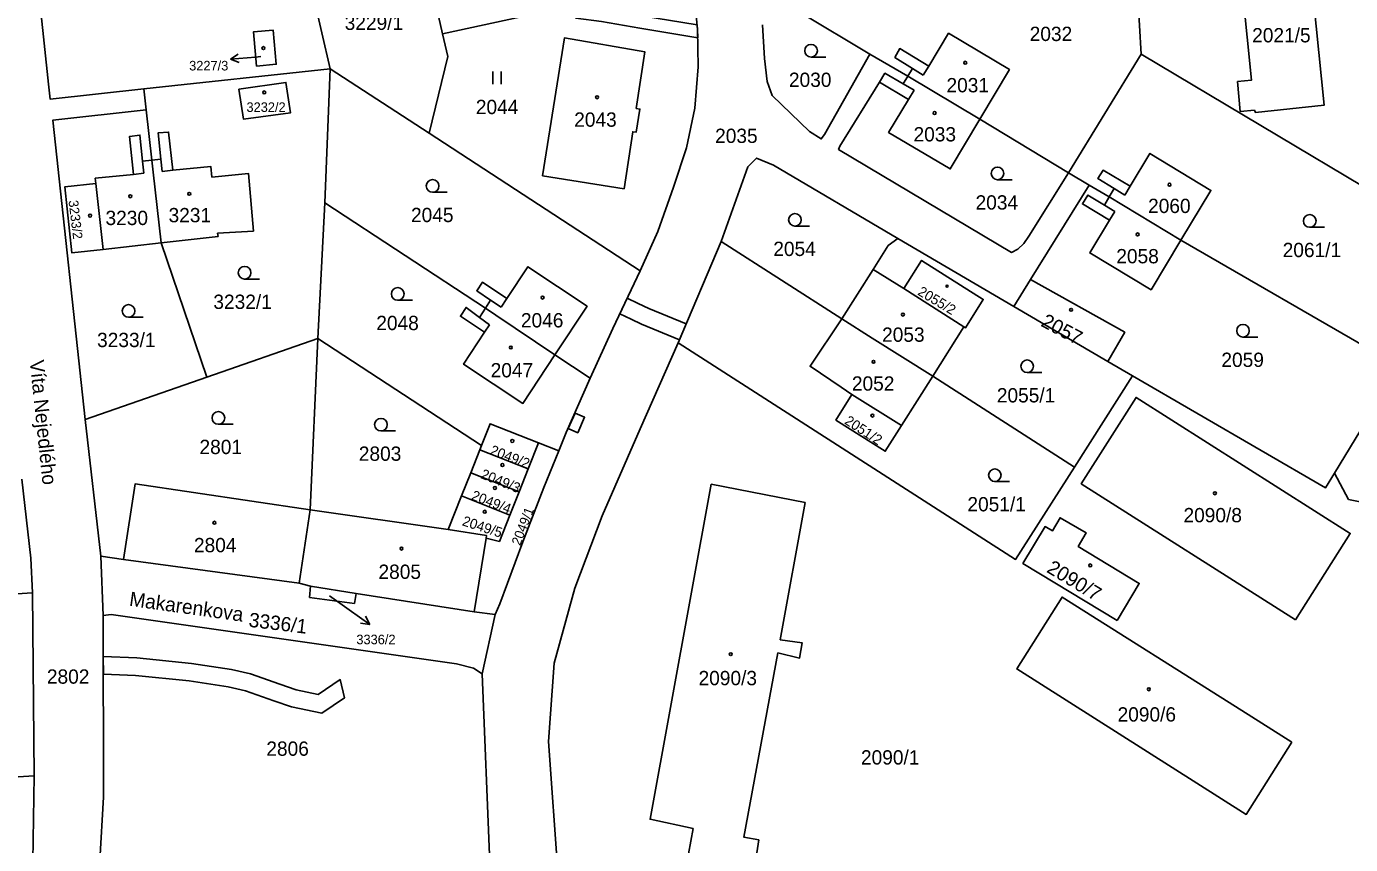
# Model space of a CAD drawing. Extents: x -869103 to -863415, y -1015889 to -1012477.
# Drawn here: x -866307 to -866149.5, y -1014543.4 to -1014446.1 of the extents above; entities that cross this region are included whole.
import ezdxf

# ---------------------------------------------------------------- set-up
doc = ezdxf.new("R2010")
doc.units = 0
for name, color, linetype in [('Hranice parcel', 7, 'Continuous'), ('Parcelní čísla', 7, 'Continuous'), ('Pop  PČ popisy', 7, 'Continuous'), ('Vnitřní kresba', 7, 'Continuous'), ('Věcná břemena k části', 7, 'Continuous'), ('Značky budov', 7, 'Continuous'), ('Značky kultur', 7, 'Continuous')]:
    doc.layers.add(name, color=color, linetype=linetype)

msp = doc.modelspace()

# ---------------------------------------------------------------- linework, layer by layer
at = {"layer": 'Hranice parcel'}
for p, q in [((-866175.13, -1014436.7), (-866174.38, -1014449.43)), ((-866273.58, -1014439.3), (-866270.86, -1014451.16)), ((-866257.47, -1014447.01), (-866246.67, -1014444.68)), ((-866206.66, -1014449.41), (-866214.86, -1014444.49)), ((-866206.66, -1014449.41), (-866202.12, -1014452.04)), ((-866183.01, -1014463.54), (-866174.38, -1014449.43)), ((-866135.49, -1014472.62), (-866174.38, -1014449.43)), ((-866293.01, -1014453.56), (-866270.86, -1014451.16)), ((-866270.86, -1014451.16), (-866271.49, -1014467.09)), ((-866259.09, -1014458.82), (-866270.86, -1014451.16)), ((-866202.12, -1014452.04), (-866193.57, -1014457.16)), ((-866292.73, -1014456.06), (-866293.01, -1014453.56)), ((-866292.06, -1014462.04), (-866292.73, -1014456.06)), ((-866193.57, -1014457.16), (-866183.01, -1014463.54)), ((-866259.09, -1014458.82), (-866233.96, -1014475.17)), ((-866180.58, -1014464.98), (-866183.01, -1014463.54)), ((-866298.71, -1014464.78), (-866297.83, -1014472.64)), ((-866187.53, -1014476.22), (-866180.58, -1014464.98)), ((-866178.18, -1014466.39), (-866180.58, -1014464.98)), ((-866169.65, -1014471.53), (-866178.18, -1014466.39)), ((-866271.49, -1014467.09), (-866272.32, -1014483.22)), ((-866271.49, -1014467.09), (-866252.39, -1014479.64)), ((-866290.94, -1014471.86), (-866284.16, -1014471.12)), ((-866229.45, -1014483.76), (-866224.33, -1014471.68)), ((-866209.97, -1014480.9), (-866224.33, -1014471.68)), ((-866203.34, -1014471.34), (-866189.52, -1014479.44)), ((-866143.69, -1014486.53), (-866169.65, -1014471.53)), ((-866297.83, -1014472.64), (-866290.94, -1014471.86)), ((-866285.53, -1014487.82), (-866290.94, -1014471.86)), ((-866206.25, -1014475.01), (-866209.97, -1014480.9)), ((-866202.63, -1014477.3), (-866206.25, -1014475.01)), ((-866189.52, -1014479.44), (-866187.53, -1014476.22)), ((-866195.46, -1014481.85), (-866202.63, -1014477.3)), ((-866178.34, -1014485.95), (-866189.52, -1014479.44)), ((-866199.18, -1014487.72), (-866195.46, -1014481.85)), ((-866272.32, -1014483.22), (-866285.53, -1014487.82)), ((-866273.23, -1014503.59), (-866272.32, -1014483.22)), ((-866272.32, -1014483.22), (-866252.84, -1014495.95)), ((-866244.11, -1014485.17), (-866239.92, -1014487.93)), ((-866175.4, -1014487.66), (-866178.34, -1014485.95)), ((-866151.4, -1014499.23), (-866143.69, -1014486.53)), ((-866285.53, -1014487.82), (-866299.97, -1014492.85)), ((-866199.18, -1014487.72), (-866202.89, -1014493.59)), ((-866182.31, -1014498.51), (-866199.18, -1014487.72)), ((-866182.31, -1014498.51), (-866175.4, -1014487.66)), ((-866202.89, -1014493.59), (-866208.78, -1014489.87)), ((-866299.97, -1014492.85), (-866298.12, -1014509.12)), ((-866253.04, -1014496.45), (-866254.13, -1014499.18)), ((-866252.84, -1014495.95), (-866253.04, -1014496.45)), ((-866253.04, -1014496.45), (-866247.28, -1014498.74)), ((-866246.05, -1014495.65), (-866247.28, -1014498.74)), ((-866243.65, -1014496.6), (-866246.05, -1014495.65)), ((-866254.13, -1014499.18), (-866255.22, -1014501.93)), ((-866254.13, -1014499.18), (-866248.37, -1014501.47)), ((-866247.28, -1014498.74), (-866248.37, -1014501.47)), ((-866248.37, -1014501.47), (-866249.46, -1014504.22)), ((-866255.22, -1014501.93), (-866256.82, -1014505.95)), ((-866255.22, -1014501.93), (-866249.46, -1014504.22)), ((-866274.52, -1014512.32), (-866273.23, -1014503.59)), ((-866256.82, -1014505.95), (-866273.23, -1014503.59)), ((-866252.29, -1014506.96), (-866253.73, -1014515.71)), ((-866298.12, -1014509.12), (-866295.41, -1014509.5)), ((-866297.84, -1014516.17), (-866298.12, -1014509.12)), ((-866295.41, -1014509.5), (-866274.52, -1014512.32)), ((-866274.52, -1014512.32), (-866273.18, -1014512.66)), ((-866306.07, -1014535.23), (-866306.24, -1014513.48)), ((-866273.18, -1014512.66), (-866267.76, -1014513.55)), ((-866267.76, -1014513.55), (-866253.73, -1014515.71)), ((-866253.73, -1014515.71), (-866251.23, -1014516.05)), ((-866251.23, -1014516.05), (-866252.75, -1014523.11)), ((-866306.07, -1014535.23), (-866310.81, -1014535.52))]:
    msp.add_line(p, q, dxfattribs=at)
for points in [[(-866262.06, -1014426.88), (-866259.63, -1014437.54), (-866257.47, -1014447.01)], [(-866293.01, -1014453.56), (-866304.17, -1014454.77), (-866304.36, -1014453), (-866306.78, -1014430.1), (-866304.7, -1014428.53)], [(-866160.89, -1014456.08), (-866160.79, -1014456.34), (-866152.63, -1014455.5), (-866154.51, -1014436.67), (-866162.78, -1014437.55), (-866161.26, -1014452.53), (-866162.92, -1014452.68), (-866162.6, -1014456.23), (-866160.89, -1014456.08)], [(-866227.71, -1014440.6), (-866227.14, -1014446.48), (-866227.07, -1014450.92), (-866227.49, -1014455.83), (-866228.45, -1014460.55), (-866229.99, -1014465.24), (-866231.89, -1014470.52), (-866233.96, -1014475.17)], [(-866219.44, -1014445.94), (-866219.2, -1014449.92), (-866218.86, -1014452.67), (-866218.26, -1014454.34), (-866213.82, -1014458.63), (-866212.44, -1014459.5), (-866212.04, -1014458.99), (-866206.66, -1014449.41)], [(-866279.6, -1014450.83), (-866279.97, -1014446.77), (-866277.63, -1014446.56), (-866277.26, -1014450.62), (-866279.6, -1014450.83)], [(-866257.47, -1014447.01), (-866256.86, -1014449.69), (-866259.09, -1014458.82)], [(-866234.44, -1014455.89), (-866233.42, -1014449.13), (-866242.98, -1014447.5), (-866245.59, -1014463.88), (-866235.88, -1014465.42), (-866234.86, -1014458.64), (-866234.46, -1014458.7), (-866234.01, -1014455.96), (-866234.44, -1014455.89)], [(-866193.57, -1014457.16), (-866190.05, -1014451.25), (-866197.29, -1014446.93), (-866199.65, -1014450.83), (-866203.1, -1014448.75), (-866203.68, -1014449.81), (-866201.57, -1014451.12), (-866202.12, -1014452.04)], [(-866281.72, -1014453.59), (-866281.15, -1014457.16), (-866275.58, -1014456.41), (-866276.1, -1014452.78), (-866281.72, -1014453.59)], [(-866205.5, -1014452.74), (-866210.24, -1014460.35), (-866210.38, -1014460.75), (-866189.82, -1014472.99), (-866189.04, -1014472.6), (-866188.32, -1014471.93), (-866187.74, -1014471.06), (-866183.01, -1014463.54)], [(-866202.12, -1014452.04), (-866202.68, -1014452.96), (-866204.87, -1014451.69), (-866205.5, -1014452.74)], [(-866205.5, -1014452.74), (-866202.05, -1014454.81), (-866204.42, -1014458.72), (-866197.09, -1014463.07), (-866193.57, -1014457.16)], [(-866299.97, -1014492.85), (-866303.84, -1014457.28), (-866292.73, -1014456.06)], [(-866292.06, -1014462.04), (-866293.15, -1014462.15), (-866293.47, -1014459.05), (-866294.73, -1014459.22), (-866294.25, -1014463.71), (-866298.78, -1014464.17), (-866298.71, -1014464.78)], [(-866279.98, -1014470.45), (-866280.56, -1014463.63), (-866284.91, -1014464.04), (-866285.05, -1014462.76), (-866289.58, -1014463.23), (-866290.06, -1014458.69), (-866291.3, -1014458.77), (-866290.97, -1014461.92), (-866292.06, -1014462.04)], [(-866105.99, -1014458.82), (-866117.63, -1014476.02), (-866116.92, -1014476.56), (-866133.47, -1014498.56), (-866138.91, -1014504.56), (-866149.72, -1014502.36), (-866151.4, -1014499.23)], [(-866290.94, -1014471.86), (-866291.9, -1014463.46), (-866292.06, -1014462.04)], [(-866224.33, -1014471.68), (-866221.17, -1014462.82), (-866220.14, -1014461.77), (-866218.1, -1014462.6), (-866203.34, -1014471.34)], [(-866169.65, -1014471.53), (-866166.09, -1014465.62), (-866173.34, -1014461.22), (-866175.69, -1014465.11), (-866178.91, -1014463.22), (-866179.52, -1014464.21), (-866177.58, -1014465.4), (-866178.18, -1014466.39)], [(-866297.83, -1014472.64), (-866301.56, -1014473.06), (-866302.39, -1014465.19), (-866298.71, -1014464.78)], [(-866178.18, -1014466.39), (-866178.76, -1014467.36), (-866180.71, -1014466.18), (-866181.38, -1014467.22), (-866178.15, -1014469.17), (-866180.5, -1014473.06), (-866173.2, -1014477.44), (-866169.65, -1014471.53)], [(-866284.16, -1014471.12), (-866284.23, -1014470.71), (-866279.98, -1014470.45)], [(-866206.25, -1014475.01), (-866204.46, -1014472.18), (-866203.34, -1014471.34)], [(-866252.39, -1014479.64), (-866251.76, -1014478.67), (-866253.41, -1014477.55), (-866252.74, -1014476.54), (-866249.82, -1014478.47), (-866247.33, -1014474.7), (-866240.29, -1014479.4), (-866244.11, -1014485.17)], [(-866202.63, -1014477.3), (-866200.5, -1014473.94), (-866193.16, -1014478.59), (-866195.29, -1014481.96), (-866195.46, -1014481.85)], [(-866233.96, -1014475.17), (-866237.21, -1014482.04), (-866239.92, -1014487.93)], [(-866178.34, -1014485.95), (-866176.33, -1014482.49), (-866187.53, -1014476.22)], [(-866252.39, -1014479.64), (-866253.1, -1014480.72), (-866254.67, -1014479.54), (-866255.36, -1014480.59), (-866252.47, -1014482.49), (-866254.98, -1014486.29), (-866247.92, -1014490.94), (-866244.11, -1014485.17)], [(-866252.39, -1014479.64), (-866251.14, -1014480.47), (-866244.11, -1014485.17)], [(-866208.78, -1014489.87), (-866210.06, -1014489.01), (-866213.77, -1014486.52), (-866209.97, -1014480.9)], [(-866199.18, -1014487.72), (-866206.36, -1014483.18), (-866209.97, -1014480.9)], [(-866244.89, -1014531.13), (-866244.21, -1014521.83), (-866241.75, -1014512.93), (-866238.49, -1014504.31), (-866233.99, -1014493.98), (-866229.45, -1014483.76)], [(-866229.45, -1014483.76), (-866189.32, -1014509.5), (-866182.31, -1014498.51)], [(-866239.92, -1014487.93), (-866242.76, -1014494.42), (-866243.65, -1014496.6)], [(-866175.4, -1014487.66), (-866152.47, -1014500.99), (-866151.4, -1014499.23)], [(-866202.89, -1014493.59), (-866204.82, -1014496.64), (-866210.7, -1014492.92), (-866208.78, -1014489.87)], [(-866156.04, -1014516.66), (-866149.51, -1014506.4), (-866174.98, -1014490.24), (-866181.51, -1014500.5), (-866156.04, -1014516.66)], [(-866246.05, -1014495.65), (-866251.82, -1014493.36), (-866252.84, -1014495.95)], [(-866243.65, -1014496.6), (-866245.44, -1014500.95), (-866247.91, -1014507.39), (-866250.68, -1014514.78), (-866251.23, -1014516.05)], [(-866306.24, -1014513.48), (-866306.47, -1014509.33), (-866307.52, -1014499.97)], [(-866295.41, -1014509.5), (-866294.03, -1014500.49), (-866273.23, -1014503.59)], [(-866225.51, -1014500.55), (-866232.8, -1014540.38), (-866227.65, -1014541.5)], [(-866217.61, -1014520.61), (-866215.02, -1014521.23), (-866214.71, -1014519.41), (-866217.32, -1014519.04), (-866214.36, -1014502.74), (-866225.51, -1014500.55)], [(-866249.46, -1014504.22), (-866250.71, -1014507.36), (-866252.29, -1014506.96)], [(-866177.23, -1014516.77), (-866174.62, -1014512.35), (-866181.87, -1014507.95), (-866180.94, -1014506.32), (-866184.03, -1014504.54), (-866184.92, -1014506.09), (-866185.82, -1014505.58), (-866188.44, -1014509.97), (-866177.23, -1014516.77)], [(-866256.82, -1014505.95), (-866252.24, -1014506.66), (-866252.29, -1014506.96)], [(-866306.24, -1014513.48), (-866313.12, -1014513.9), (-866314.13, -1014513.97), (-866322.69, -1014514.6)], [(-866267.76, -1014513.55), (-866267.96, -1014514.72), (-866273.3, -1014514.01), (-866273.18, -1014512.66)], [(-866156.45, -1014531.23), (-866162.39, -1014527.47), (-866183.78, -1014513.98), (-866189.19, -1014522.52), (-866167.76, -1014536.09), (-866161.88, -1014539.81), (-866156.45, -1014531.23)], [(-866298.23, -1014545.3), (-866297.79, -1014537.75), (-866297.84, -1014516.17)], [(-866297.84, -1014516.17), (-866296.9, -1014516.03), (-866255.83, -1014521.91), (-866253.79, -1014522.42), (-866252.75, -1014523.11)], [(-866219.84, -1014542.82), (-866221.64, -1014542.52), (-866217.61, -1014520.61)], [(-866252.75, -1014523.11), (-866251.85, -1014545.62), (-866251.59, -1014552.32)], [(-866239.33, -1014563.34), (-866241.17, -1014558), (-866243.17, -1014550.45), (-866243.74, -1014547.16), (-866244.89, -1014531.13)], [(-866310.49, -1014570.24), (-866307.92, -1014562.25), (-866306.24, -1014547.91), (-866306.07, -1014535.23)], [(-866227.65, -1014541.5), (-866228.21, -1014544.51), (-866220.34, -1014545.93), (-866219.84, -1014542.82)]]:
    msp.add_lwpolyline(points, dxfattribs=at)
at = {"layer": 'Pop  PČ popisy'}
for p, q in [((-866282.72, -1014450.02), (-866281.77, -1014449.44)), ((-866279.73, -1014449.76), (-866282.72, -1014450.02)), ((-866282.72, -1014450.02), (-866281.68, -1014450.43)), ((-866279.09, -1014449.7), (-866279.73, -1014449.76)), ((-866270.91, -1014513.81), (-866268.57, -1014515.49)), ((-866268.57, -1014515.49), (-866266.14, -1014517.25)), ((-866266.14, -1014517.25), (-866267.25, -1014517.07)), ((-866266.14, -1014517.25), (-866266.66, -1014516.26))]:
    msp.add_line(p, q, dxfattribs=at)
at = {"layer": 'Vnitřní kresba'}
for p, q in [((-866201.57, -1014451.12), (-866200.31, -1014451.93)), ((-866200.31, -1014451.93), (-866199.65, -1014450.83)), ((-866202.68, -1014452.96), (-866201.39, -1014453.71)), ((-866201.39, -1014453.71), (-866202.05, -1014454.81)), ((-866293.15, -1014462.15), (-866293, -1014463.57)), ((-866290.97, -1014461.92), (-866290.82, -1014463.36)), ((-866293, -1014463.57), (-866294.25, -1014463.71)), ((-866290.82, -1014463.36), (-866289.58, -1014463.23)), ((-866177.58, -1014465.4), (-866176.33, -1014466.17)), ((-866176.33, -1014466.17), (-866175.69, -1014465.11)), ((-866178.76, -1014467.36), (-866177.51, -1014468.12)), ((-866177.51, -1014468.12), (-866178.15, -1014469.17)), ((-866250.51, -1014479.52), (-866251.76, -1014478.67)), ((-866250.51, -1014479.52), (-866249.82, -1014478.47)), ((-866251.9, -1014481.62), (-866253.1, -1014480.72)), ((-866252.47, -1014482.49), (-866251.9, -1014481.62))]:
    msp.add_line(p, q, dxfattribs=at)
at = {"layer": 'Věcná břemena k části'}
for points in [[(-866241.97, -1014443.67), (-866241.64, -1014445.13), (-866238.58, -1014445.54), (-866234.02, -1014446.33), (-866227.12, -1014447.48), (-866227.14, -1014446.48), (-866227.19, -1014445.94), (-866233.77, -1014444.85), (-866238.35, -1014444.06), (-866240.41, -1014443.78), (-866240.51, -1014443.36)], [(-866236.38, -1014480.29), (-866235.06, -1014480.92), (-866233.8, -1014481.53), (-866229.29, -1014483.38), (-866228.49, -1014481.5), (-866232.96, -1014479.67), (-866234.22, -1014479.06), (-866235.51, -1014478.45)], [(-866236.38, -1014480.29), (-866235.06, -1014480.92), (-866233.8, -1014481.53), (-866229.29, -1014483.38), (-866228.49, -1014481.5), (-866232.96, -1014479.67), (-866234.22, -1014479.06), (-866235.51, -1014478.45)], [(-866242.54, -1014493.92), (-866241.39, -1014494.43), (-866240.58, -1014492.59), (-866241.72, -1014492.09)], [(-866297.83, -1014521.03), (-866297.82, -1014523.12), (-866293.99, -1014523.29), (-866287.61, -1014523.94), (-866282.98, -1014524.64), (-866280.9, -1014525.1), (-866277.55, -1014526.32), (-866275.45, -1014527.02), (-866271.83, -1014527.77), (-866269.15, -1014525.97), (-866269.65, -1014523.79), (-866272.27, -1014525.55), (-866274.91, -1014525), (-866276.85, -1014524.34), (-866280.32, -1014523.08), (-866282.6, -1014522.58), (-866287.35, -1014521.86), (-866293.83, -1014521.21)]]:
    msp.add_lwpolyline(points, close=True, dxfattribs=at)
at = {"layer": 'Značky budov'}
for centre, radius in [((-866278.79, -1014448.7), 0.175), ((-866195.31, -1014450.44), 0.175), ((-866278.69, -1014453.97), 0.175), ((-866239.1, -1014454.54), 0.175), ((-866198.95, -1014456.42), 0.175), ((-866171.01, -1014464.94), 0.175), ((-866294.62, -1014466.32), 0.175), ((-866287.6, -1014466.03), 0.175), ((-866299.4, -1014468.62), 0.175), ((-866174.8, -1014470.85), 0.175), ((-866197.47, -1014477.01), 0.123), ((-866245.58, -1014478.36), 0.175), ((-866202.72, -1014480.38), 0.175), ((-866182.72, -1014479.82), 0.175), ((-866249.36, -1014484.3), 0.175), ((-866206.22, -1014486), 0.175), ((-866206.35, -1014492.39), 0.175), ((-866249.18, -1014495.41), 0.175), ((-866250.36, -1014498.27), 0.175), ((-866251.25, -1014501), 0.175), ((-866165.61, -1014501.63), 0.175), ((-866252.46, -1014503.83), 0.175), ((-866284.61, -1014505.13), 0.175), ((-866262.36, -1014508.2), 0.175), ((-866180.44, -1014510.21), 0.175), ((-866223.2, -1014520.76), 0.175), ((-866173.47, -1014524.93), 0.175)]:
    msp.add_circle(centre, radius, dxfattribs=at)
at = {"layer": 'Značky kultur'}
for p, q in [((-866213.65, -1014449.77), (-866211.9, -1014449.77)), ((-866251.51, -1014453), (-866251.51, -1014451.5)), ((-866250.51, -1014453), (-866250.51, -1014451.5)), ((-866191.47, -1014464.35), (-866189.72, -1014464.35)), ((-866258.66, -1014465.84), (-866256.91, -1014465.84)), ((-866215.57, -1014469.87), (-866213.82, -1014469.87)), ((-866154.33, -1014470), (-866152.58, -1014470)), ((-866281.02, -1014476.16), (-866279.27, -1014476.16)), ((-866262.81, -1014478.68), (-866261.06, -1014478.68)), ((-866294.83, -1014480.7), (-866293.08, -1014480.7)), ((-866162.27, -1014483.06), (-866160.52, -1014483.06)), ((-866187.94, -1014487.28), (-866186.19, -1014487.28)), ((-866284.14, -1014493.42), (-866282.39, -1014493.42)), ((-866264.81, -1014494.22), (-866263.06, -1014494.22)), ((-866191.79, -1014500.23), (-866190.04, -1014500.23))]:
    msp.add_line(p, q, dxfattribs=at)
for centre in [(-866213.65, -1014449.02), (-866191.47, -1014463.6), (-866258.66, -1014465.09), (-866215.57, -1014469.12), (-866154.33, -1014469.25), (-866281.02, -1014475.41), (-866262.81, -1014477.93), (-866294.83, -1014479.95), (-866162.27, -1014482.31), (-866187.94, -1014486.53), (-866284.14, -1014492.67), (-866264.81, -1014493.47), (-866191.79, -1014499.48)]:
    msp.add_circle(centre, 0.75, dxfattribs=at)

# ---------------------------------------------------------------- texts
at = {"layer": 'Parcelní čísla'}
for s, height, p in [('3229/1', 1.7, (-866269.12, -1014446.54)), ('2032', 1.7, (-866187.64, -1014447.86)), ('2021/5', 1.7, (-866161.18, -1014448.02)), ('3227/3', 1.139, (-866287.62, -1014451.36)), ('2030', 1.7, (-866216.28, -1014453.32)), ('2031', 1.7, (-866197.54, -1014453.96)), ('3232/2', 1.139, (-866280.8, -1014456.29)), ('2044', 1.7, (-866253.52, -1014456.55)), ('2043', 1.7, (-866241.82, -1014458.05)), ('2035', 1.7, (-866225.06, -1014459.98)), ('2033', 1.7, (-866201.46, -1014459.8)), ('2034', 1.7, (-866194.08, -1014467.9)), ('2060', 1.7, (-866173.56, -1014468.31)), ('3230', 1.7, (-866297.57, -1014469.74)), ('3231', 1.7, (-866290.07, -1014469.41)), ('2045', 1.7, (-866261.23, -1014469.39)), ('2054', 1.7, (-866218.14, -1014473.42)), ('2058', 1.7, (-866177.34, -1014474.29)), ('2061/1', 1.7, (-866157.55, -1014473.55)), ('3232/1', 1.7, (-866284.74, -1014479.71)), ('2048', 1.7, (-866265.36, -1014482.23)), ('2046', 1.7, (-866248.16, -1014481.91)), ('3233/1', 1.7, (-866298.57, -1014484.25)), ('2053', 1.7, (-866205.2, -1014483.62)), ('2059', 1.7, (-866164.84, -1014486.61)), ('2047', 1.7, (-866251.76, -1014487.85)), ('2052', 1.7, (-866208.79, -1014489.43)), ('2055/1', 1.7, (-866191.55, -1014490.83)), ('2801', 1.7, (-866286.39, -1014496.97)), ('2803', 1.7, (-866267.44, -1014497.77)), ('2051/1', 1.7, (-866195.05, -1014503.78)), ('2090/8', 1.7, (-866169.35, -1014505.08)), ('2804', 1.7, (-866287.05, -1014508.64)), ('2805', 1.7, (-866265.1, -1014511.81)), ('3336/2', 1.139, (-866267.73, -1014519.58)), ('2802', 1.7, (-866304.54, -1014524.27)), ('2090/3', 1.7, (-866227.03, -1014524.45)), ('2090/6', 1.7, (-866177.19, -1014528.77)), ('2806', 1.7, (-866278.44, -1014532.84)), ('2090/1', 1.7, (-866207.71, -1014533.88))]:
    msp.add_text(s, height=height, dxfattribs=at).set_placement(p)
for s, height, rotation, p in [('3233/2', 1.139, 277, (-866301.97, -1014466.85)), ('2055/2', 1.19, 329, (-866201.06, -1014477.97)), ('2057', 1.7, 332, (-866186.42, -1014481.69)), ('2051/2', 1.19, 327, (-866209.76, -1014493.3)), ('2049/2', 1.19, 339, (-866251.93, -1014496.97)), ('2049/3', 1.19, 338, (-866253.04, -1014499.8)), ('2049/4', 1.19, 339, (-866254.15, -1014502.35)), ('2049/5', 1.19, 342, (-866255.23, -1014505.42)), ('2049/1', 1.139, 69, (-866248.25, -1014507.92)), ('2090/7', 1.7, 329, (-866185.74, -1014510.94)), ('3336/1', 1.7, 353, (-866280.6, -1014517.49))]:
    msp.add_text(s, height=height, rotation=rotation, dxfattribs=at).set_placement(p)
at = {"layer": 'Pop  PČ popisy'}
for s, rotation, p in [('Víta Nejedlého', 276, (-866306.59, -1014485.87)), ('Makarenkova', 352, (-866294.81, -1014515))]:
    msp.add_text(s, height=1.7, rotation=rotation, dxfattribs=at).set_placement(p)

doc.saveas('drawing.dxf')
